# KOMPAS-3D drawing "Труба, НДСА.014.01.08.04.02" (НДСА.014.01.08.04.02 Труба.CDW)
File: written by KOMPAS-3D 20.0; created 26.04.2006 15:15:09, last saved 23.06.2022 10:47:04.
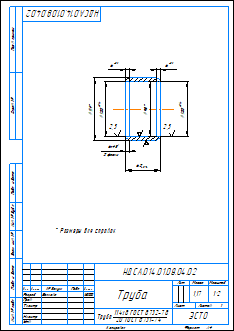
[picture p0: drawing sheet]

Sheet 1: A4, portrait

Document properties: Автор: Устинов А.В.; Организация: ЭСТО-Вакуум; Полное имя файла: НДСА.014.01.08.04.02 Труба.m3d; 244675298101: <item xmlns="http://appius.ru/pdm" xmlns:xs="http://www.w3.org/2001/XMLSchema" xmlns:xsi="http://www.w3.org/2001/XMLSchema-instance" xsi:type="item">  <element xmlns:d2p1="http://v8.1c.ru/8.1/data/enterprise/current-config" xsi:type="d2p1:CatalogRef.aps_Элемен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; PLM_CDWXDTO: <item xmlns="http://appius.ru/pdm" xmlns:xs="http://www.w3.org/2001/XMLSchema" xmlns:xsi="http://www.w3.org/2001/XMLSchema-instance" xsi:type="item">  <element xmlns:d2p1="http://v8.1c.ru/8.1/data/enterprise/current-config" xsi:type="d2p1:CatalogRef.aps_Элемен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; Масса: 1.17099

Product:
- Part/product: Труба  | designation НДСА.014.01.08.04.02
    Материал: Труба$d114х8 ГОСТ 8732-78;20 ГОСТ 8731-74$ (density 7859 kg/m3)
    Масса: 1.17099

Title block, sheet 1: Наименование: Труба; designation: НДСА.014.01.08.04.02; Материал: Труба 114х8 ГОСТ 8732-78 20 ГОСТ 8731-74; Масса: 1,17; scale: 1:2; Количество листов документа: 1; organisation: ЭСТО; Форматы листов документа: A4; stored path: D:\WorkPDM\Устинов А.В\8b0af0dc-f3da-4f92-ad11-61854faa3fd1\УКРД.789.01.03.10.04 Труба.cdw; Разработал: Волкова; Разработал, date: 16.01.2020
Table, sheet 1:
  0;Material:V399CD8922A934364BF9D3DB1A16B3F75;Sortament:VACA86AD6B524487FA06521D22EE88F1C^SortamentEx:VAAA4FC64CE1B4DEDB4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

Views: Вид 1, Спереди, Разрез А-А
Referenced files in E:\НДСА.014.01.08.00.00 Гидроподъемник\: НДСА.014.01.08.04.02 Труба.m3d
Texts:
  НДСА.014.01.08.04.02 Труба
Dimensions and other numbers on the sheet: 98; 6; 2 фаски; 114; 100; 2,5; 62; 1:2; 1; 1,17; 16.01.2020

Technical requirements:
  * Размеры для справок.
